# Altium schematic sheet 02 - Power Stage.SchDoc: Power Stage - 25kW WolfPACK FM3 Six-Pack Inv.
size 431 x 279 mm; Date: 07/2023; DocumentNumber: CRD25DA12N-FMC; Revision: 1.1; SheetNumber: 2; SheetTotal: 8; SheetSize: B
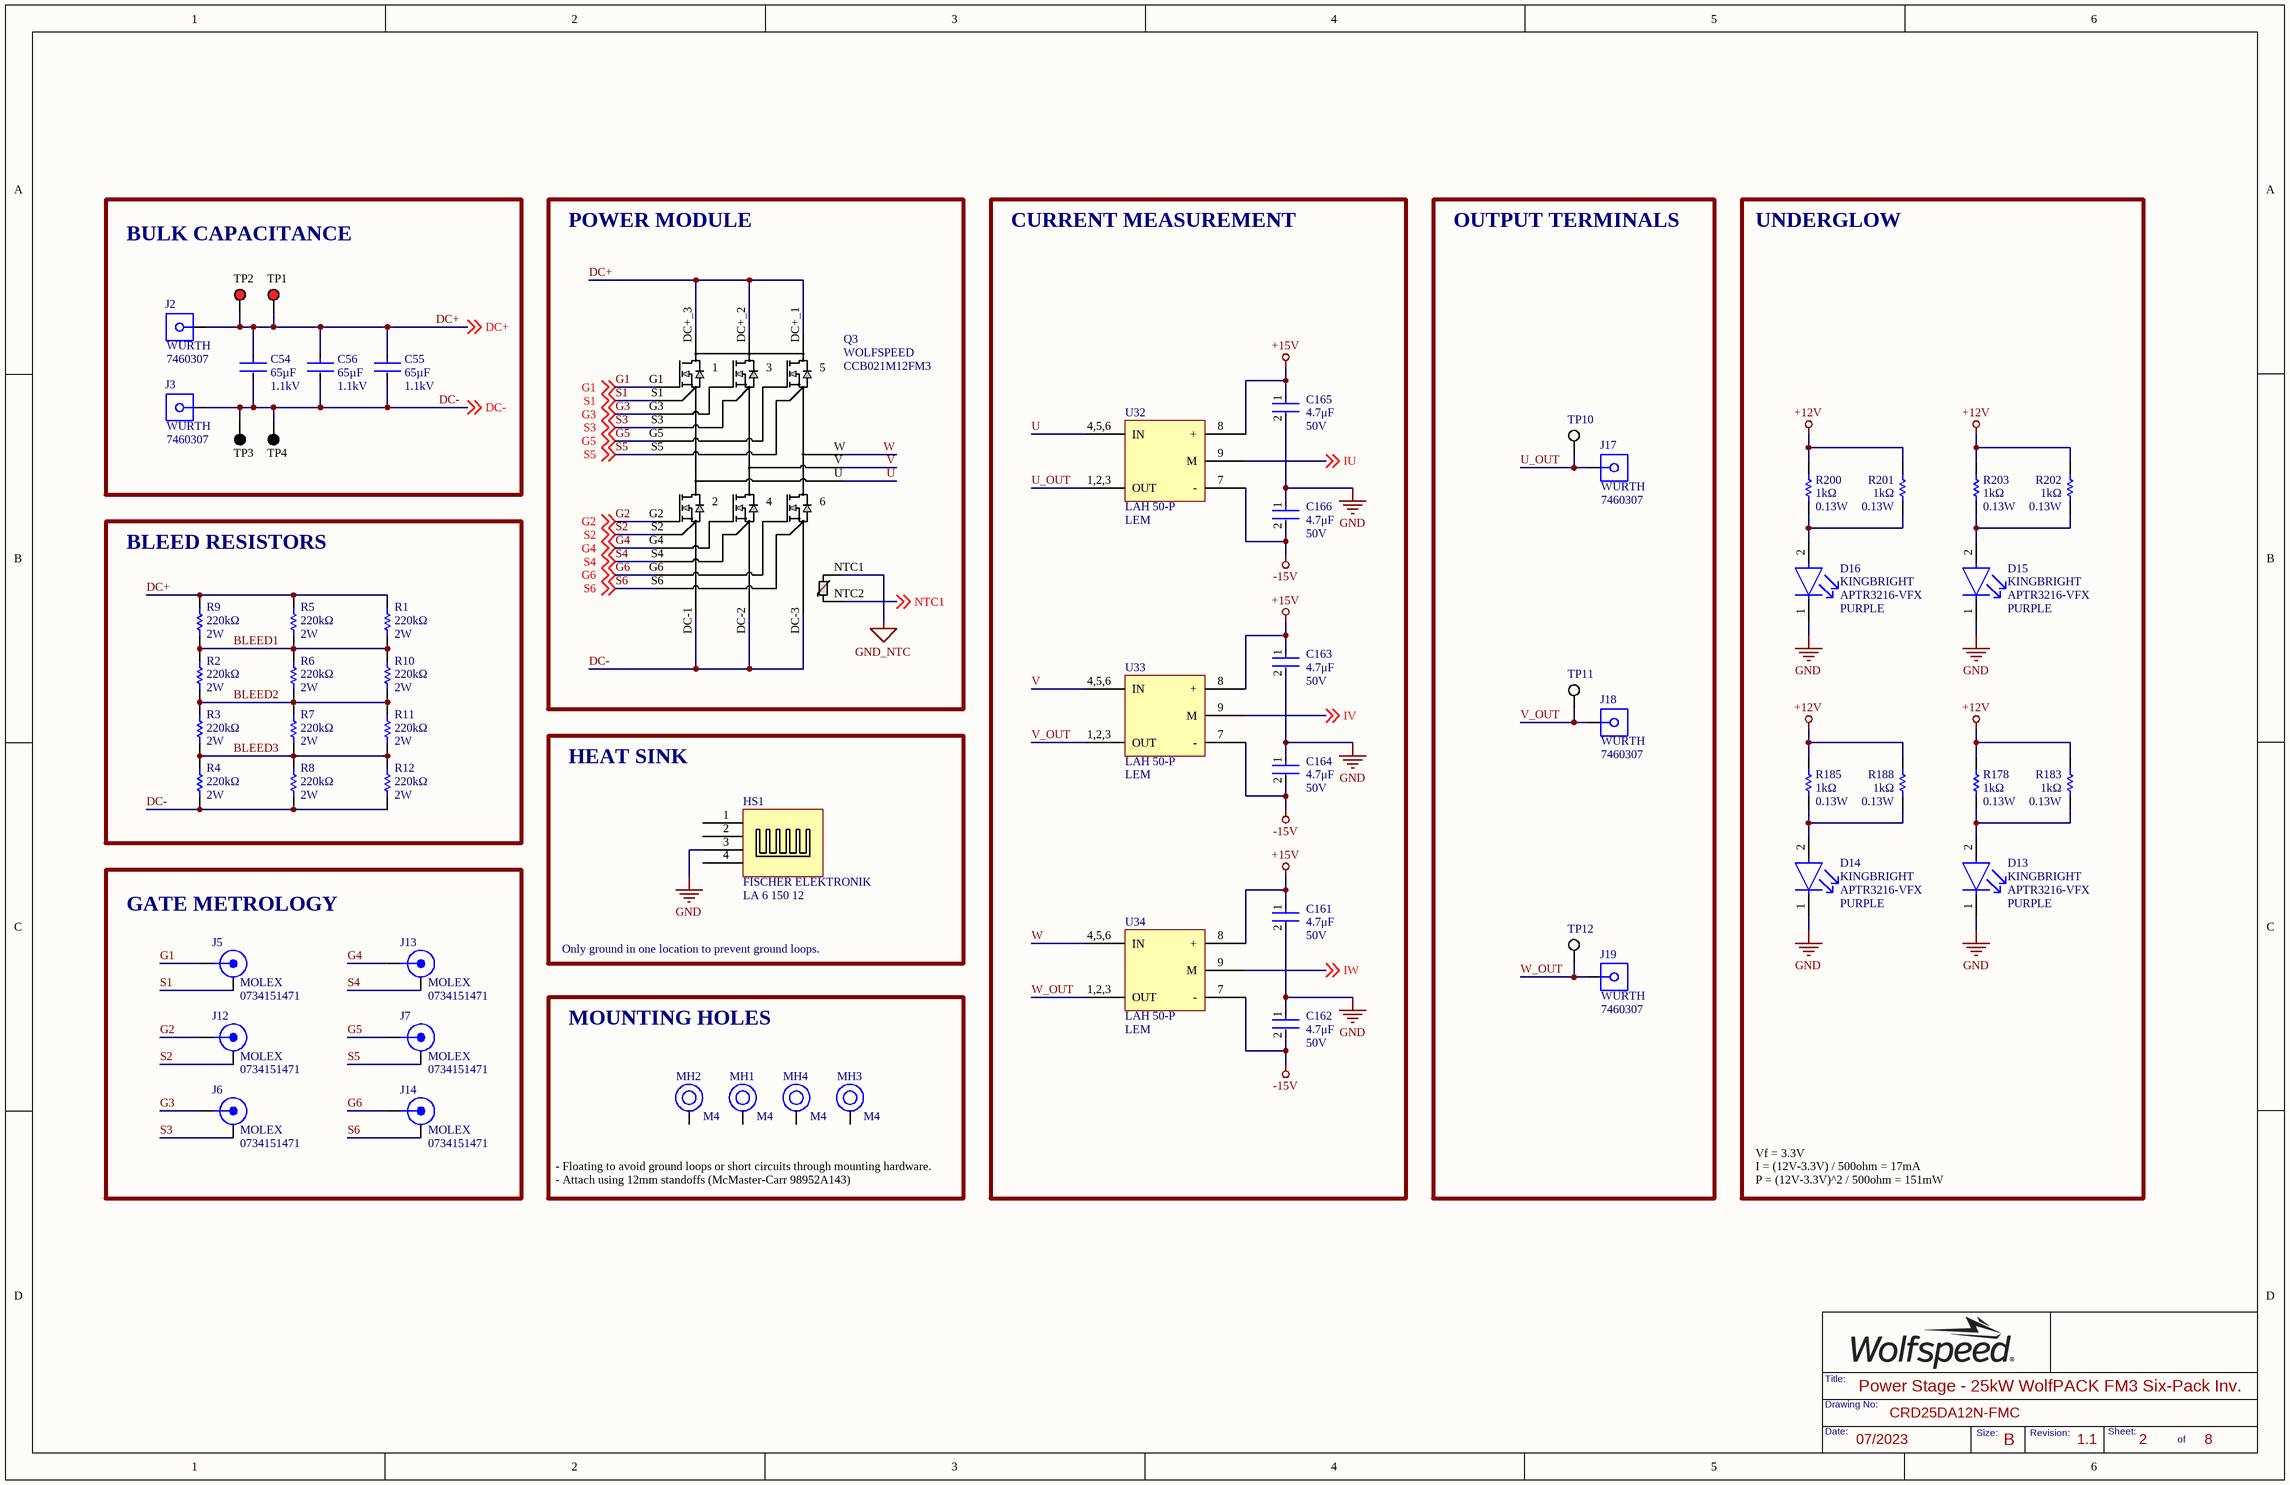
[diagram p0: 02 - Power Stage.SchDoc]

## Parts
C54  Voltage: 1.1kV  Capacitance: 65µF  [C4AQQEW5650A3BJ]  (hidden comment: C4AQQEW5650A3BJ)
C55  Voltage: 1.1kV  Capacitance: 65µF  [C4AQQEW5650A3BJ]  (hidden comment: C4AQQEW5650A3BJ)
C56  Voltage: 1.1kV  Capacitance: 65µF  [C4AQQEW5650A3BJ]  (hidden comment: C4AQQEW5650A3BJ)
C161  Voltage Rating: 50V  Capacitance: 4.7μF  [FP-CL31-IPC_C]  (hidden comment: CL31B475KBHNFNE)
C162  Voltage Rating: 50V  Capacitance: 4.7μF  [FP-CL31-IPC_C]  (hidden comment: CL31B475KBHNFNE)
C163  Voltage Rating: 50V  Capacitance: 4.7μF  [FP-CL31-IPC_C]  (hidden comment: CL31B475KBHNFNE)
C164  Voltage Rating: 50V  Capacitance: 4.7μF  [FP-CL31-IPC_C]  (hidden comment: CL31B475KBHNFNE)
C165  Voltage Rating: 50V  Capacitance: 4.7μF  [FP-CL31-IPC_C]  (hidden comment: CL31B475KBHNFNE)
C166  Voltage Rating: 50V  Capacitance: 4.7μF  [FP-CL31-IPC_C]  (hidden comment: CL31B475KBHNFNE)
D13  Manufacturer Print: KINGBRIGHT  Color: PURPLE  [FP-APTR3216SECK-MFG]  (hidden comment: APTR3216-VFX)
D14  Manufacturer Print: KINGBRIGHT  Color: PURPLE  [FP-APTR3216SECK-MFG]  (hidden comment: APTR3216-VFX)
D15  Manufacturer Print: KINGBRIGHT  Color: PURPLE  [FP-APTR3216SECK-MFG]  (hidden comment: APTR3216-VFX)
D16  Manufacturer Print: KINGBRIGHT  Color: PURPLE  [FP-APTR3216SECK-MFG]  (hidden comment: APTR3216-VFX)
HS1  LA 6 150 12  Manufacturer: FISCHER ELEKTRONIK  [LA 6 150 12]
J2  Manufacturer Print: WURTH  [7460307]  (hidden comment: 7460307)
J3  Manufacturer Print: WURTH  [7460307]  (hidden comment: 7460307)
J5  0734151471  Manufacturer Print: MOLEX  [FP-73415-1471-MFG]
J6  0734151471  Manufacturer Print: MOLEX  [FP-73415-1471-MFG]
J7  0734151471  Manufacturer Print: MOLEX  [FP-73415-1471-MFG]
J12  0734151471  Manufacturer Print: MOLEX  [FP-73415-1471-MFG]
J13  0734151471  Manufacturer Print: MOLEX  [FP-73415-1471-MFG]
J14  0734151471  Manufacturer Print: MOLEX  [FP-73415-1471-MFG]
J17  Manufacturer Print: WURTH  [7460307]  (hidden comment: 7460307)
J18  Manufacturer Print: WURTH  [7460307]  (hidden comment: 7460307)
J19  Manufacturer Print: WURTH  [7460307]  (hidden comment: 7460307)
MH1  Size: M4  [MH_M4_P]  (hidden comment: MH_M4_P)
MH2  Size: M4  [MH_M4_P]  (hidden comment: MH_M4_P)
MH3  Size: M4  [MH_M4_P]  (hidden comment: MH_M4_P)
MH4  Size: M4  [MH_M4_P]  (hidden comment: MH_M4_P)
Q3  CCB021M12FM3  Manufacturer Print: WOLFSPEED  [FM3_SIX-PACK_3PHASE_CRW]
R1  Power Rating: 2W  Resistance: 220kΩ  [FP-CRGP2512-IPC_C]  (hidden comment: CRGP2512F220K)
R2  Power Rating: 2W  Resistance: 220kΩ  [FP-CRGP2512-IPC_C]  (hidden comment: CRGP2512F220K)
R3  Power Rating: 2W  Resistance: 220kΩ  [FP-CRGP2512-IPC_C]  (hidden comment: CRGP2512F220K)
R4  Power Rating: 2W  Resistance: 220kΩ  [FP-CRGP2512-IPC_C]  (hidden comment: CRGP2512F220K)
R5  Power Rating: 2W  Resistance: 220kΩ  [FP-CRGP2512-IPC_C]  (hidden comment: CRGP2512F220K)
R6  Power Rating: 2W  Resistance: 220kΩ  [FP-CRGP2512-IPC_C]  (hidden comment: CRGP2512F220K)
R7  Power Rating: 2W  Resistance: 220kΩ  [FP-CRGP2512-IPC_C]  (hidden comment: CRGP2512F220K)
R8  Power Rating: 2W  Resistance: 220kΩ  [FP-CRGP2512-IPC_C]  (hidden comment: CRGP2512F220K)
R9  Power Rating: 2W  Resistance: 220kΩ  [FP-CRGP2512-IPC_C]  (hidden comment: CRGP2512F220K)
R10  Power Rating: 2W  Resistance: 220kΩ  [FP-CRGP2512-IPC_C]  (hidden comment: CRGP2512F220K)
R11  Power Rating: 2W  Resistance: 220kΩ  [FP-CRGP2512-IPC_C]  (hidden comment: CRGP2512F220K)
R12  Power Rating: 2W  Resistance: 220kΩ  [FP-CRGP2512-IPC_C]  (hidden comment: CRGP2512F220K)
R178  Resistance: 1kΩ  Power Rating: 0.13W  [RESC2013X50X30LL20T20]  (hidden comment: CRCW08051K00JNTA)
R183  Resistance: 1kΩ  Power Rating: 0.13W  [RESC2013X50X30LL20T20]  (hidden comment: CRCW08051K00JNTA)
R185  Resistance: 1kΩ  Power Rating: 0.13W  [RESC2013X50X30LL20T20]  (hidden comment: CRCW08051K00JNTA)
R188  Resistance: 1kΩ  Power Rating: 0.13W  [RESC2013X50X30LL20T20]  (hidden comment: CRCW08051K00JNTA)
R200  Resistance: 1kΩ  Power Rating: 0.13W  [RESC2013X50X30LL20T20]  (hidden comment: CRCW08051K00JNTA)
R201  Resistance: 1kΩ  Power Rating: 0.13W  [RESC2013X50X30LL20T20]  (hidden comment: CRCW08051K00JNTA)
R202  Resistance: 1kΩ  Power Rating: 0.13W  [RESC2013X50X30LL20T20]  (hidden comment: CRCW08051K00JNTA)
R203  Resistance: 1kΩ  Power Rating: 0.13W  [RESC2013X50X30LL20T20]  (hidden comment: CRCW08051K00JNTA)
TP1  5010  [KSTN-5010_V]  (value not drawn)
TP2  5010  [KSTN-5010_V]  (value not drawn)
TP3  5011  [KSTN-5011_V]  (value not drawn)
TP4  5011  [KSTN-5011_V]  (value not drawn)
TP10  5012  [KSTN-5012_V]  (value not drawn)
TP11  5012  [KSTN-5012_V]  (value not drawn)
TP12  5012  [KSTN-5012_V]  (value not drawn)
U32  LAH 50-P  Manufacturer Print: LEM  [LAH 50-P]
U33  LAH 50-P  Manufacturer Print: LEM  [LAH 50-P]
U34  LAH 50-P  Manufacturer Print: LEM  [LAH 50-P]

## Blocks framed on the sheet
BULK CAPACITANCE: C54-C56 J2 J3 TP1-TP4
POWER MODULE: Q3
CURRENT MEASUREMENT: C161-C166 U32-U34
OUTPUT TERMINALS: J17-J19 TP10-TP12
UNDERGLOW: D13-D16 R178 R183 R185 R188 R200-R203
BLEED RESISTORS: R1-R12
HEAT SINK: HS1
GATE METROLOGY: J5-J7 J12-J14
MOUNTING HOLES: MH1-MH4

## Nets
+12V: R178.2 R183.2 R185.2 R188.2 R200.2 R201.2 R202.2 R203.2
+15V: C161.1 C163.1 C165.1 U32.8(+) U33.8(+) U34.8(+)
-15V: C162.2 C164.2 C166.2 U32.7(-) U33.7(-) U34.7(-)
GND: C161.2 C162.1 C163.2 C164.1 C165.2 C166.1 D13.1(C) D14.1(C) D15.1(C) D16.1(C) HS1.3
GND_NTC: Q3.NTC1
BLEED1: R1.1 R2.2 R5.1 R6.2 R9.1 R10.2
BLEED2: R2.1 R3.2 R6.1 R7.2 R10.1 R11.2
BLEED3: R3.1 R4.2 R7.1 R8.2 R11.1 R12.2
DC+: C54.1,2(+) C55.1,2(+) C56.1,2(+) J2.1,2,3,4,5,6,7,8 Q3.DC+_1 Q3.DC+_2 Q3.DC+_3 R1.2 R5.2 R9.2 TP1.1 TP2.1 ; off-sheet DC+
DC-: C54.3,4 C55.3,4 C56.3,4 J3.1,2,3,4,5,6,7,8 Q3.DC-1 Q3.DC-2 Q3.DC-3 R4.1 R8.1 R12.1 TP3.1 TP4.1 ; off-sheet DC-
G1: J5.1(CENTER) Q3.G1 ; off-sheet G1
G2: J12.1(CENTER) Q3.G2 ; off-sheet G2
G3: J6.1(CENTER) Q3.G3 ; off-sheet G3
G4: J13.1(CENTER) Q3.G4 ; off-sheet G4
G5: J7.1(CENTER) Q3.G5 ; off-sheet G5
G6: J14.1(CENTER) Q3.G6 ; off-sheet G6
IU: U32.9(M) ; off-sheet IU
IV: U33.9(M) ; off-sheet IV
IW: U34.9(M) ; off-sheet IW
NTC1: Q3.NTC2 ; off-sheet NTC1
S1: J5.2,3,4,5(SHIELD) Q3.S1 ; off-sheet S1
S2: J12.2,3,4,5(SHIELD) Q3.S2 ; off-sheet S2
S3: J6.2,3,4,5(SHIELD) Q3.S3 ; off-sheet S3
S4: J13.2,3,4,5(SHIELD) Q3.S4 ; off-sheet S4
S5: J7.2,3,4,5(SHIELD) Q3.S5 ; off-sheet S5
S6: J14.2,3,4,5(SHIELD) Q3.S6 ; off-sheet S6
U: Q3.U U32.4,5,6(IN)
U_OUT: J17.1,2,3,4,5,6,7,8 TP10.1 U32.1,2,3(OUT)
V: Q3.V U33.4,5,6(IN)
V_OUT: J18.1,2,3,4,5,6,7,8 TP11.1 U33.1,2,3(OUT)
W: Q3.W U34.4,5,6(IN)
W_OUT: J19.1,2,3,4,5,6,7,8 TP12.1 U34.1,2,3(OUT)
NetD13_2: D13.2(A) R178.1 R183.1
NetD14_2: D14.2(A) R185.1 R188.1
NetD15_2: D15.2(A) R202.1 R203.1
NetD16_2: D16.2(A) R200.1 R201.1

Not connected (* = marked no-connect by the designer): HS1 1 2 4; MH1 1; MH2 1; MH3 1; MH4 1

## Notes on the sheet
- Only ground in one location to prevent ground loops.
- - Floating to avoid ground loops or short circuits through mounting hardware.
  - Attach using 12mm standoffs (McMaster-Carr 98952A143)
- Vf = 3.3V
  I = (12V-3.3V) / 500ohm = 17mA
  P = (12V-3.3V)^2 / 500ohm = 151mW

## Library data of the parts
C54-C56 = C4AQQEW5650A3BJ: CAP FILM 65UF 5% 1.1KVDC RAD; Manufacturer: KEMET; Value: 65µF
C161-C166 = CMP-13271-001123-1: CAP CER 4.7UF 50V X7R 1206; Manufacturer: SAMSUNG; Tolerance: 10%; Value: 4.7μF
D13-D16 = APTR3216-VFX: LED PURPLE CLEAR 1206 SMD
HS1 = LA 6 150 12: HEATSINK EXTRUSION 150MM; Manufacturer Part Number: LA6/15012V; Natural Thermal Resistance: 0.175°C/W; Power Consumption: 2.9W
J2 J3 J17-J19 = 7460307: TERM REDCUBE M4 8PIN PCB; Manufacturer: WURTH ELEKTRONIK; Current Rating: 80A; Number of Contacts: 8; Insulation: Non-Insulated
J5-J7 J12-J14 = 0734151471: CONN MMCX JACK STR 50 OHM PCB; Manufacturer Part Number: 73415-1471; Body Material: Brass; Body Plating: Gold; Impedance: 50R; Connector Type: PCB,MMCX,Coaxial; Max Frequency: 6GHz; Gender: Female
MH1-MH4 = MH_M4_P: HEX STANDOFF M4 ALUMINUM 51MM F-F; Manufacturer: MCMASTER-CARR; Manufacturer Part Number: 95947A552
Q3 = CCB021M12FM3: 1200V silicon carbide six-pack power module delivering maximum power density; Mfr_Name: Cree Wolfspeed; Type: DEV
R1-R12 = CMP-03211-002966-1: RES 220K OHM 1% 2W 2512; Manufacturer: TE; Value: 220kΩ; Temperature Coefficient: ±100ppm/°C; Tolerance: 0.01; Voltage Rating: 500V
R178 R183 R185 R188 R200-R203 = CRCW08051K00JNTA: RES SMD 1K OHM 5% 1/8W 0805; Manufacturer: VISHAY DALE; Temperature Coefficient: 200ppm/°C; Max Power Dissipation: 125mW; Voltage Rating: 150V; Value: 1kΩ
TP1 TP2 = CMP-1672-00002-4: PC TEST POINT MULTIPURPOSE RED; Manufacturer: KEYSTONE
TP3 TP4 = CMP-1672-00003-4: PC TEST POINT MULTIPURPOSE BLACK; Manufacturer: KEYSTONE
TP10-TP12 = CMP-1672-00004-4: PC TEST POINT MULTIPURPOSE WHITE; Manufacturer: KEYSTONE
U32-U34 = LAH 50-P: SENSOR CURRENT HALL 50A AC/DC; Frequency: 200kHz; Number of Channels: 1; Response Time: 0.5us; Max Supply Current: 35mA; Polarity: Bidirectional; Linearity: 0.15%; Accuracy: 0.25%; Operating Supply Voltage: 15V; Secondary Current: 25mA; Overall Height: 21mm; Overall Depth: 14.93mm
